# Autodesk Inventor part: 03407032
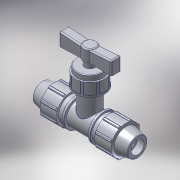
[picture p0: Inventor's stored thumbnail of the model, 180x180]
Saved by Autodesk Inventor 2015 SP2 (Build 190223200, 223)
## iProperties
Created: 2017-02
Part Number: 03407032
Material: PVC-Piping
Description: PLASSON COMPRESSION STOPTAP 32
Document SubType Name: Modeling
Designer: KIM
Mass: 92.6774 g
Surface Area: 199.44 cm^2
Volume: 66.1981 cm^3
Density: 1.4 g/cm^3
Appearance: PTFE
Author: KIM
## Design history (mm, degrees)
derived "03407.ipt"
feature "Solid1::03407.ipt"
tag "TaggingFeature1"
body "Solid1"
other parameters: "d1" = 174, "d2" = 32, "d4" = 14.5, "d5" = 20.88, "d7" = 64, "d8" = 48, "d9" = 43.5, "d11" = 4.35, "d12" = 51.2, "d13" = 120 deg, "d14" = 48, "d15" = 12 deg, "d16" = 57.6, "d18" = 1.6, "d19" = 35 deg, "d20" = 17.5 deg, "d21" = 59.52, "d23" = 0, "d25" = 360 deg, "d27" = 1.28, "d33" = 0.64, "d42" = 31.32, "d43" = 1.92, "d46" = 0.96, "d49" = 57, "d50" = 25.6, "d51" = 95, "d53" = 19, "d54" = 19, "d57" = 17.1, "d60" = 42.75, "d61" = 28.5, "d62" = 19, "d63" = 61.75, "d64" = 15.2, "d65" = 38, "d66" = 7.6, "d69" = 12.825, "d70" = 6.4125, "d71" = 41.895, "d72" = 41.4, "d74" = 0, "d75" = 16.15, "d76" = 92, "d77" = 92, "d80" = 360 deg, "d82" = 0.38, "d85" = 38, "d86" = 6 deg, "d87" = 94 deg, "d88" = 14.25, "d89" = 0, "d90" = 2, "d91" = 2, "d92" = 0.95, "d93" = 0.95, "d_" = 32, "E_" = 64, "H_" = 174, "l_" = 57, "A_" = 95, "d67" = 92, "d78" = 42.75
